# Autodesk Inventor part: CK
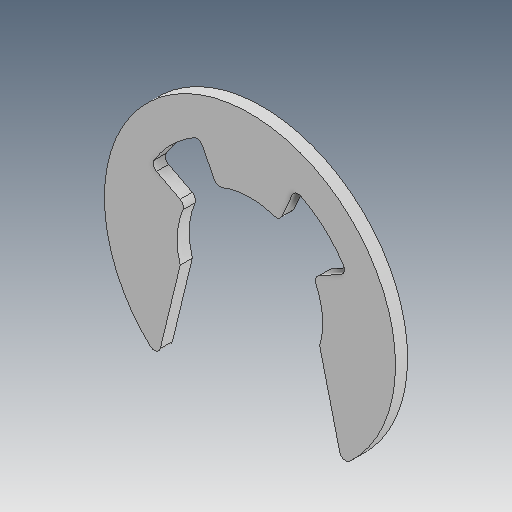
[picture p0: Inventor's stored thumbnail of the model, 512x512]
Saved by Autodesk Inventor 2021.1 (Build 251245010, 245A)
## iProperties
Created: 2019-04
Part Number: CK
Material: Ogólny
Document SubType Name: Modeling
Designer: user
Density: 1 g/cm^3
Appearance: Domyślna
Author: user
Revision Number: ÈÎºÎ
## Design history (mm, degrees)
feature "ÊäÈë1"
node "Bryła1"
